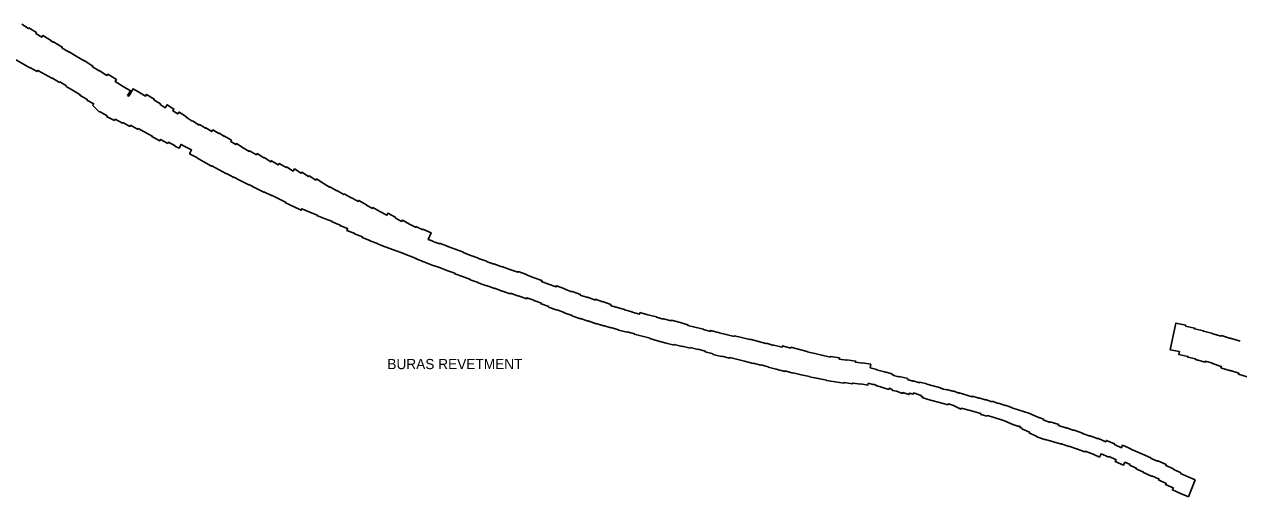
# Model space of a CAD drawing. Extents: x 2650582 to 3923188, y 277893 to 989177.
# Drawn here: x 3840315 to 3859336, y 315687 to 323086 of the extents above; entities that cross this region are included whole.
import ezdxf

# ---------------------------------------------------------------- set-up
doc = ezdxf.new("R2010")
doc.units = 0
doc.layers.add('Level 3', color=7, linetype='Continuous')

msp = doc.modelspace()

# ---------------------------------------------------------------- linework, layer by layer
at = {"layer": 'Level 3'}
for points in [[(3840274, 323086), (3840380, 323020), (3840386, 323030), (3840505, 322956), (3840496, 322943), (3840589, 322884), (3840607, 322912), (3840726, 322838), (3840723, 322833), (3840767, 322805), (3840771, 322812)], [(3840771, 322812), (3840908, 322729), (3840902, 322718), (3841006, 322655), (3841007, 322658), (3841127, 322585), (3841128, 322587), (3841250, 322512), (3841253, 322517), (3841390, 322433), (3841383, 322422), (3841486, 322359), (3841487, 322361), (3841610, 322286), (3841621, 322304), (3841758, 322221), (3841739, 322189), (3841861, 322114), (3841861, 322114), (3841976, 322046), (3841933, 321972)], [(3840974, 322124), (3840898, 322170), (3840897, 322168), (3840870, 322184), (3840866, 322177), (3840755, 322240), (3840754, 322238), (3840642, 322302), (3840640, 322299), (3840526, 322364), (3840515, 322345), (3840402, 322409), (3840401, 322407), (3840169, 322540)], [(3842563, 321221), (3842450, 321283), (3842437, 321260), (3842314, 321327), (3842318, 321335), (3842211, 321393), (3842211, 321392), (3842096, 321454), (3842090, 321443), (3841979, 321504), (3841969, 321486), (3841856, 321547), (3841851, 321537), (3841737, 321599), (3841725, 321577), (3841604, 321643), (3841611, 321655), (3841494, 321718), (3841489, 321713), (3841384, 321818), (3841404, 321838), (3841295, 321900), (3841301, 321910), (3841187, 321975), (3841192, 321983), (3841080, 322047), (3841081, 322050), (3840969, 322114), (3840974, 322124)], [(3841933, 321972), (3841951, 321962), (3842019, 322075), (3842117, 322016), (3842118, 322017), (3842215, 321963), (3842229, 321987), (3842349, 321915), (3842343, 321904), (3842450, 321840), (3842444, 321830), (3842522, 321779), (3842553, 321826), (3842657, 321758), (3842640, 321733), (3842719, 321682), (3842739, 321712), (3842856, 321636), (3842852, 321630), (3842945, 321570), (3842948, 321575)], [(3842948, 321575), (3843053, 321507), (3843060, 321518), (3843154, 321457), (3843159, 321466), (3843251, 321406), (3843268, 321433), (3843360, 321374), (3843366, 321383), (3843450, 321329), (3843453, 321335), (3843560, 321271), (3843548, 321251), (3843628, 321203), (3843637, 321218), (3843743, 321154), (3843743, 321153), (3843837, 321096), (3843843, 321107), (3843951, 321042), (3843962, 321061), (3844069, 320996), (3844070, 320998), (3844177, 320934), (3844186, 320948), (3844293, 320884), (3844307, 320907), (3844414, 320843), (3844420, 320852), (3844526, 320788), (3844548, 320821), (3844653, 320753), (3844662, 320768), (3844767, 320700), (3844776, 320713), (3844881, 320645), (3844894, 320665), (3845011, 320589), (3845010, 320586)], [(3844787, 320146), (3844662, 320196), (3844652, 320174), (3844529, 320232), (3844529, 320231), (3844517, 320237), (3844402, 320294), (3844406, 320302), (3844302, 320354), (3844300, 320352), (3844187, 320409), (3844184, 320403), (3844068, 320461), (3844065, 320456), (3843940, 320518), (3843941, 320522), (3843833, 320576), (3843830, 320571), (3843706, 320636), (3843706, 320637), (3843599, 320694), (3843596, 320689), (3843483, 320751), (3843480, 320746), (3843357, 320812), (3843357, 320813), (3843252, 320870), (3843249, 320863), (3843126, 320930), (3843128, 320934), (3843015, 320995), (3843017, 320998), (3842903, 321060), (3842930, 321109), (3842928, 321110), (3842934, 321118), (3842830, 321174), (3842830, 321173), (3842770, 321206), (3842738, 321146), (3842674, 321180), (3842676, 321183), (3842573, 321239), (3842563, 321221)], [(3845010, 320586), (3845096, 320535), (3845101, 320543), (3845208, 320478), (3845212, 320484), (3845319, 320420), (3845324, 320429), (3845432, 320367), (3845435, 320372), (3845543, 320309), (3845554, 320327), (3845675, 320257), (3845673, 320254), (3845766, 320200), (3845774, 320215), (3845884, 320154), (3845885, 320156), (3845994, 320096), (3846011, 320126), (3846133, 320058), (3846130, 320052), (3846226, 319998), (3846237, 320018), (3846359, 319950), (3846359, 319950), (3846443, 319907), (3846448, 319917), (3846555, 319868), (3846558, 319876), (3846687, 319822), (3846643, 319718), (3846705, 319695), (3846703, 319691), (3846818, 319649), (3846820, 319656), (3846952, 319608), (3846950, 319604), (3847061, 319563), (3847061, 319563), (3847192, 319515)], [(3847177, 319134), (3847178, 319136), (3847057, 319180), (3847059, 319187), (3846949, 319227), (3846949, 319226), (3846818, 319275), (3846705, 319316), (3846704, 319315), (3846573, 319364), (3846574, 319366), (3846451, 319411), (3846454, 319419), (3846334, 319464), (3846334, 319465), (3846211, 319510), (3846212, 319511), (3846100, 319552), (3846100, 319552), (3845969, 319600), (3845969, 319602), (3845846, 319647), (3845848, 319651), (3845726, 319695), (3845728, 319701), (3845606, 319746), (3845611, 319758), (3845489, 319802), (3845491, 319808), (3845367, 319858), (3845379, 319888), (3845258, 319937), (3845260, 319941), (3845138, 319990), (3845141, 319996), (3845029, 320041), (3845029, 320041), (3844899, 320093), (3844901, 320099), (3844787, 320146)], [(3847192, 319515), (3847190, 319511), (3847311, 319466), (3847311, 319466), (3847431, 319421), (3847430, 319419), (3847554, 319374), (3847554, 319373), (3847668, 319331), (3847670, 319336), (3847794, 319290), (3847795, 319291), (3847919, 319245), (3847920, 319248), (3848044, 319202), (3848048, 319214), (3848179, 319166), (3848178, 319163), (3848303, 319117), (3848421, 319073), (3848415, 319058), (3848524, 319018), (3848524, 319018), (3848644, 318974), (3848650, 318990), (3848781, 318942), (3848781, 318939), (3848892, 318898), (3848894, 318903), (3849025, 318855), (3849022, 318846), (3849134, 318805), (3849137, 318813), (3849259, 318768), (3849263, 318779), (3849369, 318740), (3849371, 318746), (3849504, 318700), (3849498, 318683)], [(3849389, 318371), (3849385, 318361), (3849273, 318400), (3849271, 318396), (3849149, 318441), (3849147, 318436), (3849028, 318480), (3849025, 318473), (3848893, 318521), (3848894, 318523), (3848771, 318568), (3848772, 318573), (3848661, 318614), (3848659, 318609), (3848527, 318658), (3848530, 318664), (3848410, 318708), (3848414, 318717), (3848293, 318762), (3848294, 318765), (3848188, 318804), (3848181, 318787), (3848056, 318833), (3848055, 318829), (3847931, 318874), (3847927, 318863), (3847803, 318909), (3847802, 318906), (3847678, 318951), (3847677, 318948), (3847553, 318993), (3847553, 318991), (3847422, 319039), (3847422, 319040), (3847299, 319086), (3847301, 319088), (3847177, 319134)], [(3849498, 318683), (3849582, 318654), (3849583, 318657), (3849718, 318619), (3849716, 318612), (3849835, 318583), (3849834, 318576), (3849950, 318546), (3849956, 318570), (3850082, 318537), (3850082, 318537), (3850218, 318502), (3850217, 318498), (3850323, 318470), (3850324, 318474), (3850447, 318442), (3850450, 318452), (3850586, 318417), (3850585, 318414), (3850708, 318381), (3850706, 318371), (3850816, 318342), (3850817, 318345), (3850816, 318345), (3850953, 318310), (3850951, 318304), (3851061, 318275), (3851065, 318292), (3851201, 318256), (3851200, 318252), (3851307, 318226), (3851308, 318230), (3851433, 318199), (3851436, 318209), (3851680, 318149), (3851681, 318153), (3851817, 318120), (3851816, 318116), (3851931, 318086), (3851933, 318091), (3852056, 318058), (3852057, 318061), (3852183, 318027), (3852188, 318049), (3852317, 318014), (3852321, 318028), (3852457, 317992), (3852456, 317991), (3852576, 317963), (3852575, 317958), (3852699, 317931), (3852698, 317928), (3852828, 317900), (3852827, 317897), (3852942, 317874), (3852944, 317885), (3853082, 317861), (3853079, 317842), (3853195, 317824), (3853196, 317831), (3853336, 317812), (3853333, 317794), (3853442, 317780), (3853443, 317783), (3853572, 317762), (3853563, 317706)], [(3853534, 317463), (3853529, 317436), (3853415, 317454), (3853415, 317451), (3853290, 317467), (3853289, 317456), (3853154, 317474), (3853153, 317466), (3853017, 317488), (3853016, 317484), (3852878, 317508), (3852879, 317513), (3852750, 317539), (3852749, 317536), (3852612, 317566), (3852613, 317568), (3852483, 317597), (3852484, 317598), (3852359, 317627), (3852358, 317624), (3852229, 317659), (3852226, 317648), (3852091, 317684), (3851965, 317718), (3851966, 317721), (3851854, 317751), (3851852, 317746), (3851733, 317778), (3851733, 317776), (3851596, 317810), (3851596, 317810), (3851364, 317867), (3851361, 317857), (3851238, 317887), (3851237, 317883), (3851100, 317917), (3851102, 317924), (3850978, 317957), (3850980, 317967), (3850871, 317996), (3850869, 317991), (3850746, 318024), (3850743, 318015), (3850621, 318047), (3850619, 318039), (3850495, 318072), (3850492, 318062), (3850370, 318094), (3850369, 318092), (3850234, 318128), (3850234, 318131), (3850114, 318163), (3850116, 318170), (3849868, 318235), (3849870, 318239), (3849759, 318268), (3849757, 318263), (3849621, 318297), (3849623, 318302), (3849501, 318336), (3849500, 318333), (3849389, 318371)], [(3859356, 318124), (3859208, 318172), (3859205, 318164), (3859067, 318210), (3859063, 318202), (3858929, 318238), (3858930, 318241), (3858784, 318279), (3858785, 318285), (3858643, 318316), (3858645, 318329), (3858503, 318360), (3858505, 318373), (3858353, 318406), (3858264, 317990), (3858407, 317960), (3858397, 317916), (3858539, 317885), (3858537, 317872), (3858661, 317846), (3858657, 317834), (3858809, 317794), (3858813, 317808), (3858925, 317778), (3858923, 317773), (3859063, 317728), (3859056, 317706), (3859206, 317658), (3859208, 317665), (3859336, 317624), (3859331, 317607), (3859470, 317563)], [(3853563, 317706), (3853667, 317682), (3853665, 317674), (3853786, 317645), (3853786, 317642), (3853907, 317613), (3853904, 317600), (3853933, 317592), (3853931, 317584), (3854014, 317564), (3854016, 317571), (3854151, 317536), (3854148, 317523)], [(3854783, 317126), (3854472, 317211), (3854379, 317241), (3854384, 317257), (3854358, 317264), (3854361, 317274), (3854244, 317312), (3854239, 317292), (3854177, 317308), (3854169, 317287), (3854075, 317317), (3854071, 317306), (3853976, 317340), (3853912, 317353), (3853913, 317361), (3853864, 317387), (3853855, 317367), (3853759, 317400), (3853757, 317395), (3853659, 317427), (3853661, 317431), (3853631, 317443), (3853611, 317447), (3853610, 317444), (3853534, 317463)], [(3854148, 317523), (3854232, 317496), (3854235, 317503), (3854338, 317473), (3854340, 317480), (3854450, 317453), (3854449, 317448), (3854530, 317427), (3854531, 317430)], [(3854531, 317430), (3854667, 317394), (3854665, 317389), (3854713, 317373), (3854757, 317362), (3854759, 317368), (3854859, 317338), (3854863, 317344), (3854953, 317308), (3854955, 317315), (3855160, 317251), (3855164, 317261), (3855263, 317230), (3855266, 317236), (3855365, 317202), (3855368, 317209), (3855469, 317175), (3855471, 317181), (3855573, 317146), (3855575, 317151), (3855676, 317114), (3855678, 317119), (3855783, 317082), (3855782, 317080), (3855881, 317047), (3855882, 317050), (3855981, 317014), (3855983, 317018), (3856049, 316994), (3856050, 316996)], [(3855944, 316759), (3855910, 316770), (3855916, 316786), (3855895, 316793), (3855892, 316787), (3855796, 316820), (3855667, 316875), (3855488, 316931), (3855490, 316935), (3855398, 316957), (3855395, 316949), (3855296, 316977), (3855299, 316989), (3855131, 317037), (3854991, 317072), (3854983, 317057), (3854867, 317117), (3854866, 317115), (3854790, 317144), (3854783, 317126)], [(3856050, 316996), (3856179, 316939), (3856178, 316936), (3856279, 316902), (3856275, 316890), (3856380, 316852), (3856382, 316858), (3856517, 316817), (3856512, 316800), (3856628, 316764), (3856630, 316769), (3856755, 316725), (3856757, 316730), (3856890, 316683), (3856888, 316679), (3857008, 316637), (3857009, 316641), (3857136, 316596), (3857138, 316599), (3857252, 316545), (3857263, 316570), (3857392, 316513), (3857388, 316503), (3857499, 316454), (3857517, 316494), (3857646, 316436), (3857644, 316433), (3857828, 316351), (3857830, 316354), (3857959, 316297), (3857956, 316291), (3858066, 316243), (3858069, 316249), (3858199, 316192), (3858192, 316177), (3858314, 316123), (3858310, 316116), (3858429, 316063), (3858424, 316053), (3858544, 316000), (3858542, 315996), (3858653, 315951), (3858547, 315687)], [(3858547, 315687), (3858415, 315740), (3858415, 315742), (3858297, 315794), (3858311, 315825), (3858191, 315878), (3858200, 315896), (3858081, 315949), (3858088, 315964), (3857975, 316014), (3857972, 316007), (3857843, 316065), (3857846, 316071), (3857727, 316124), (3857732, 316136), (3857629, 316182), (3857633, 316191), (3857553, 316227), (3857531, 316179), (3857402, 316236), (3857416, 316266), (3857304, 316316), (3857300, 316307), (3857180, 316360), (3857155, 316308), (3857057, 316355), (3857057, 316354), (3856932, 316398), (3856928, 316389), (3856795, 316436), (3856796, 316439), (3856677, 316481), (3856675, 316476), (3856559, 316517), (3856558, 316512), (3856435, 316549), (3856435, 316546), (3856309, 316585), (3856307, 316578), (3856174, 316626), (3856176, 316631), (3856054, 316686), (3856059, 316696), (3855940, 316749), (3855944, 316759)]]:
    msp.add_lwpolyline(points, dxfattribs=at)

# ---------------------------------------------------------------- texts
msp.add_text('BURAS REVETMENT', height=160, dxfattribs=at).set_placement((3846001, 317685))

doc.saveas('drawing.dxf')
